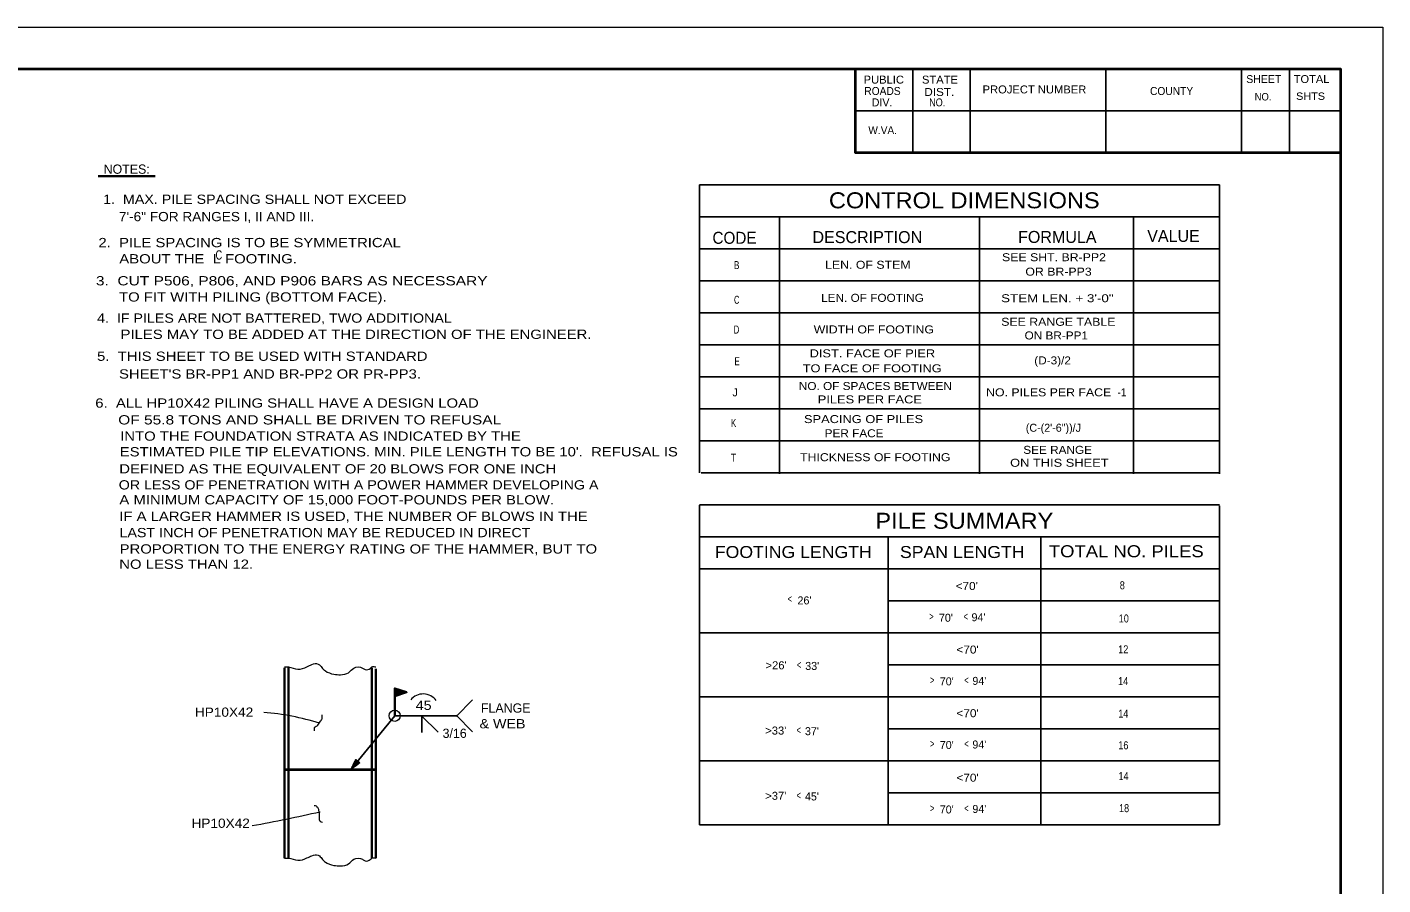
# Model space of a CAD drawing. Extents: x 144 to 252, y 360 to 425.
# Drawn here: x 203.8 to 251.81, y 395.1 to 425.48 of the extents above; entities that cross this region are included whole.
import ezdxf
from ezdxf.enums import TextEntityAlignment as Align

# ---------------------------------------------------------------- set-up
doc = ezdxf.new("R2010")
doc.units = 0
doc.header["$LTSCALE"] = 0.13
for name, color, linetype, lineweight in [('1', 7, 'Continuous', 40), ('16', 7, 'Continuous', 13), ('18', 7, 'Continuous', 13), ('3', 7, 'Continuous', 13), ('30', 7, 'Continuous', 35), ('5', 7, 'Continuous', 35)]:
    doc.layers.add(name, color=color, linetype=linetype, lineweight=lineweight)

msp = doc.modelspace()

# ---------------------------------------------------------------- linework, layer by layer
at = {"layer": '1', "lineweight": 13}
msp.add_line((143.8112, 425.4823), (251.8112, 425.4823), dxfattribs=at)
at = {"layer": '1', "lineweight": 25}
for p, q in [((235.1642, 423.9913), (235.1642, 421.0393)), ((237.2012, 423.9913), (237.2012, 421.0393)), ((242.0042, 423.9913), (242.0042, 421.0393)), ((246.8012, 423.9913), (246.8012, 421.0393)), ((248.5052, 423.9913), (248.5052, 421.0393)), ((233.1242, 422.5183), (250.3172, 422.5183)), ((227.6108, 419.8997), (246.0275, 419.8997)), ((227.6108, 419.8997), (227.6108, 409.6906)), ((246.0275, 419.8997), (246.0275, 409.6627)), ((227.6108, 418.7607), (246.0275, 418.7607)), ((230.4442, 418.7607), (230.4442, 409.6627)), ((237.5275, 418.7607), (237.5275, 409.6627)), ((242.9788, 418.7607), (242.9788, 409.6627)), ((227.6108, 417.6273), (246.0275, 417.6273)), ((227.6108, 416.494), (246.0275, 416.494)), ((227.6108, 415.3607), (246.0275, 415.3607)), ((227.6108, 414.2273), (246.0275, 414.2273)), ((227.6108, 413.094), (246.0275, 413.094)), ((227.6108, 411.9607), (246.0275, 411.9607)), ((227.6108, 410.8273), (246.0275, 410.8273)), ((227.6762, 409.694), (246.0275, 409.694)), ((227.6108, 408.5607), (246.0275, 408.5607)), ((227.6108, 408.547), (227.6108, 397.2273)), ((246.0275, 408.5192), (246.0275, 397.2273)), ((227.6108, 407.4273), (246.0275, 407.4273)), ((234.2933, 407.4313), (234.2933, 397.2273)), ((239.7031, 407.4034), (239.7031, 397.2273)), ((227.6108, 406.294), (246.0275, 406.294)), ((234.2696, 405.1607), (246.0275, 405.1607)), ((234.2935, 405.1607), (246.0275, 405.1607)), ((227.6108, 404.0273), (246.0275, 404.0273)), ((227.6108, 404.0273), (246.0275, 404.0273)), ((234.2696, 402.894), (246.0275, 402.894)), ((234.2935, 402.894), (246.0275, 402.894)), ((227.6108, 401.7607), (246.0275, 401.7607)), ((234.2703, 400.6273), (246.0275, 400.6273)), ((227.6108, 399.494), (246.0275, 399.494)), ((234.2703, 398.3607), (246.0275, 398.3607)), ((227.6108, 397.2273), (246.0275, 397.2273))]:
    msp.add_line(p, q, dxfattribs=at)
at = {"layer": '1'}
for points in [[(250.3172, 361.9183), (250.3172, 423.9913), (149.8112, 423.9913), (149.8112, 361.9183), (230.3642, 361.9183)], [(233.1242, 423.9913), (233.1242, 421.0393), (250.3172, 421.0393)]]:
    msp.add_lwpolyline(points, dxfattribs=at)
at = {"layer": '16'}
msp.add_line((251.8112, 425.4823), (251.8112, 360.4183), dxfattribs=at)
at = {"layer": '18', "lineweight": 40}
msp.add_line((212.8978, 399.1897), (216.1891, 399.1897), dxfattribs=at)
at = {"layer": '18'}
msp.add_circle((216.8197, 401.0882), 0.1992, dxfattribs=at)
for centre, radius, start, end in [((217.8308, 401.2918), 0.5699, 36.25159, 141.15152), ((211.561, 392.7422), 8.487, 72.16357, 85.80287), ((199.8884, 461.4898), 65.3832, 280.4785, 282.62405)]:
    msp.add_arc(centre, radius, start, end, dxfattribs=at)
for points in [[(213.9855, 400.5587), (214.003, 400.6987), (214.0731, 400.7337), (214.1256, 400.7862), (214.2132, 400.9263), (214.2482, 400.9788), (214.2482, 401.0664), (214.2482, 401.1189)], [(213.968, 397.9148), (214.038, 397.8973), (214.0556, 397.8798), (214.1081, 397.8098), (214.1256, 397.7398), (214.1431, 397.6347), (214.1431, 397.5822), (214.1431, 397.4772), (214.1781, 397.3546), (214.2657, 397.3196)]]:
    msp.add_spline(points, degree=3, dxfattribs=at)
at = {"layer": '3', "lineweight": 25}
for p, q in [((219.5754, 401.6492), (218.9924, 401.0667)), ((216.8234, 401.0874), (215.2632, 399.1897)), ((216.8234, 401.0874), (219.0234, 401.0874)), ((218.3567, 400.5062), (217.7739, 401.0887)), ((217.7802, 400.4942), (217.7802, 401.0942)), ((219.5752, 400.5254), (218.9924, 401.1079))]:
    msp.add_line(p, q, dxfattribs=at)
at = {"layer": '3'}
msp.add_line((215.4387, 399.5452), (215.2567, 399.1742), dxfattribs=at)
at = {"layer": '3', "lineweight": 35}
msp.add_lwpolyline([(216.8234, 401.0874), (216.8234, 402.0596), (217.2401, 401.9207), (216.8234, 401.7818), (216.8374, 402.0304), (217.2093, 401.9228), (216.8393, 401.8038), (216.8432, 402.006), (217.1621, 401.9247), (216.8467, 401.8173), (216.8564, 401.9796), (217.1093, 401.9247), (216.8602, 401.8341), (216.8677, 401.9494), (217.0602, 401.9211), (216.877, 401.8511), (216.8827, 401.9324), (216.9998, 401.9192), (216.8734, 401.8643), (216.894, 401.9077), (216.9582, 401.9153), (216.9073, 401.8926)], dxfattribs=at)
at = {"layer": '3'}
msp.add_lwpolyline([(215.4417, 399.5422), (215.5854, 399.4247), (215.2567, 399.1742)], dxfattribs=at)
at = {"layer": '3', "lineweight": 25}
for points in [[(215.5704, 399.4284), (215.2854, 399.2064), (215.5527, 399.4449), (215.2914, 399.2252), (215.5307, 399.4559), (215.3094, 399.2489), (215.5182, 399.4587), (215.3067, 399.2679), (215.5017, 399.4649), (215.3377, 399.3102), (215.4584, 399.4527), (215.3459, 399.3292), (215.4554, 399.4734), (215.3564, 399.3532), (215.4414, 399.4832), (215.3749, 399.3802), (215.4294, 399.4912), (215.3719, 399.4009)], [(215.3862, 399.4204), (215.2894, 399.2159), (215.3602, 399.3357)], [(215.5424, 399.4167), (215.4484, 399.3512), (215.5164, 399.3959), (215.4027, 399.3134), (215.4889, 399.4277), (215.3819, 399.3507), (215.4667, 399.4717), (215.3919, 399.3919), (215.4672, 399.4384), (215.3877, 399.3644), (215.5182, 399.4274)], [(215.4944, 399.4029), (215.4257, 399.3549), (215.5097, 399.4327), (215.3707, 399.3034)], [(215.5092, 399.4837), (215.5682, 399.4259), (215.4462, 399.5294), (215.5502, 399.4222), (215.4307, 399.5222), (215.5544, 399.4094), (215.4282, 399.5079), (215.5414, 399.4002), (215.4232, 399.4972), (215.5329, 399.3922)]]:
    msp.add_spline(points, degree=3, dxfattribs=at)
at = {"layer": '30'}
msp.add_line((206.3227, 420.2052), (208.3405, 420.2052), dxfattribs=at)
at = {"layer": '5'}
for p, q in [((212.9222, 402.7922), (212.9225, 396.047)), ((213.0621, 402.7922), (213.0623, 396.0469)), ((216.0155, 402.7922), (216.0157, 396.0472)), ((216.1554, 402.7482), (216.1557, 396.0471))]:
    msp.add_line(p, q, dxfattribs=at)
at = {"layer": '5', "lineweight": 13}
for points in [[(212.9225, 402.8192), (213.0623, 402.8191), (213.3893, 402.7417), (213.7145, 402.823), (213.8859, 402.9043), (214.1117, 402.9222), (214.1568, 402.8954), (214.2651, 402.7689), (214.3646, 402.6787), (214.6623, 402.5611), (214.8974, 402.5432), (215.1862, 402.6154), (215.3757, 402.7779), (215.6828, 402.7781), (215.7731, 402.7237), (215.9538, 402.7688), (216.0157, 402.8193), (216.1557, 402.8193)], [(212.9225, 396.047), (213.0623, 396.0469), (213.3893, 395.9695), (213.7145, 396.0508), (213.8859, 396.1322), (214.1117, 396.1501), (214.1568, 396.1232), (214.2651, 395.9967), (214.3646, 395.9065), (214.6623, 395.7889), (214.8974, 395.771), (215.1862, 395.8433), (215.3757, 396.0057), (215.6828, 396.0059), (215.7731, 395.9515), (215.9538, 395.9967), (216.0157, 396.0472), (216.1557, 396.0471)]]:
    msp.add_spline(points, degree=3, dxfattribs=at)

# ---------------------------------------------------------------- texts
at = {"layer": '1'}
for s, height, width, p in [('PUBLIC', 0.282, 1.05, (234.1385, 423.4813)), ('STATE', 0.282, 1.05, (236.1275, 423.4813)), ('PROJECT NUMBER', 0.282, 1.05, (239.4737, 423.1333)), ('TOTAL', 0.2791, 1.05, (249.2858, 423.5023)), ('ROADS', 0.285, 0.95, (234.0921, 423.0763)), ('DIST.', 0.282, 1.1, (236.1036, 423.0433)), ('NO.', 0.282, 0.85, (236.0299, 422.6743)), ('COUNTY', 0.285, 0.95, (244.3296, 423.0763)), ('NO.', 0.264, 0.95, (247.5679, 422.8843)), ('SHTS', 0.261, 1.1, (249.2505, 422.9053)), ('W.VA.', 0.282, 0.95, (234.0992, 421.6903)), ('NO. OF SPACES BETWEEN', 0.2833, 1.1, (233.8403, 412.6273)), ('PILES PER FACE', 0.2833, 1.2, (233.6452, 412.1532)), ('NO. PILES PER FACE', 0.2833, 1.15, (239.9767, 412.4042)), ('-1', 0.2833, 0.95, (242.5707, 412.4042)), ('K', 0.2833, 0.75, (228.8199, 411.3164)), ('SPACING OF PILES', 0.2833, 1.2, (233.422, 411.4558)), ('PER FACE', 0.2833, 1.1, (233.0873, 410.9538)), ('SEE RANGE', 0.2833, 1.1, (240.2944, 410.3659)), ('T', 0.2833, 0.8, (228.8199, 410.0848)), ('THICKNESS OF FOOTING', 0.2833, 1.15, (233.8362, 410.1062)), ('ON THIS SHEET', 0.2833, 1.2, (240.3544, 409.9088))]:
    msp.add_text(s, height=height, dxfattribs=dict(at, width=width)).set_placement(p, align=Align.CENTER)
for s, height, p in [('SHEET', 0.2791, (247.5948, 423.5023)), ('DIV.', 0.282, (234.0783, 422.6743)), ('J', 0.2833, (228.8756, 412.4042)), ('(C-(2\'-6"))/J', 0.2833, (240.144, 411.149))]:
    msp.add_text(s, height=height, dxfattribs=at).set_placement(p, align=Align.CENTER)
for s, height, width, p in [('CONTROL DIMENSIONS', 0.5667, 1.1, (232.1952, 419.0638)), ('CODE', 0.425, 0.95, (228.0727, 417.8058)), ('B', 0.2833, 0.75, (228.835, 416.9092)), ('LEN. OF STEM', 0.2833, 1.15, (232.0607, 416.9223)), ('SEE SHT. BR-PP2', 0.2833, 1.15, (238.3252, 417.1897)), ('OR BR-PP3', 0.2833, 1.15, (239.1519, 416.6783)), ('C', 0.2833, 0.65, (228.835, 415.6819)), ('LEN. OF FOOTING', 0.2833, 1.1, (231.9213, 415.7509)), ('STEM LEN. + 3\'-0"', 0.2833, 1.25, (238.2929, 415.7367)), ('D', 0.2833, 0.65, (228.8284, 414.628)), ('WIDTH OF FOOTING', 0.2833, 1.15, (231.657, 414.6318)), ('SEE RANGE TABLE', 0.2833, 1.15, (238.2973, 414.9025)), ('ON BR-PP1', 0.2833, 1.1, (239.124, 414.4191)), ('DIST. FACE OF PIER', 0.2833, 1.2, (231.5117, 413.7842)), ('(D-3)/2', 0.2833, 1.1, (239.4676, 413.5342)), ('E', 0.2833, 0.75, (228.8502, 413.5051)), ('TO FACE OF FOOTING', 0.2833, 1.2, (231.266, 413.2544)), ('PILE SUMMARY', 0.5667, 1.1, (233.8408, 407.7117)), ('FOOTING LENGTH', 0.425, 1.1, (228.1563, 406.6768)), ('SPAN LENGTH', 0.425, 1.1, (234.711, 406.6767)), ('TOTAL NO. PILES', 0.425, 1.15, (239.9827, 406.7047)), ("<70'", 0.2833, 1.1, (236.6829, 405.5454)), ('8', 0.2833, 0.85, (242.4947, 405.5699)), ('<', 0.2833, 0.65, (230.737, 405.0905)), ('>', 0.2833, 0.65, (235.7448, 404.4672)), ('<', 0.2833, 0.65, (236.9617, 404.4646)), ('10', 0.2833, 0.85, (242.4577, 404.3938)), ("<70'", 0.2833, 1.1, (236.7129, 403.2917)), ('12', 0.2833, 0.85, (242.4385, 403.3004)), (">26'", 0.2833, 1.05, (229.9488, 402.7347)), ('<', 0.2833, 0.65, (231.0592, 402.7532)), ('>', 0.2833, 0.65, (235.7748, 402.2136)), ('<', 0.2833, 0.65, (236.9917, 402.2109)), ('14', 0.2833, 0.85, (242.4357, 402.1735)), ("<70'", 0.2833, 1.1, (236.7129, 401.0381)), ('14', 0.2833, 0.85, (242.4398, 401.0231)), (">33'", 0.2833, 1.05, (229.939, 400.4234)), ('<', 0.2833, 0.65, (231.0493, 400.4418)), ('>', 0.2833, 0.65, (235.7748, 399.9599)), ('<', 0.2833, 0.65, (236.9917, 399.9572)), ('16', 0.2833, 0.85, (242.4424, 399.9002)), ("<70'", 0.2833, 1.1, (236.7129, 398.7543)), ('14', 0.2833, 0.85, (242.4492, 398.8111)), (">37'", 0.2833, 1.05, (229.939, 398.1121)), ('<', 0.2833, 0.65, (231.0493, 398.1305)), ('>', 0.2833, 0.65, (235.7748, 397.6762)), ('<', 0.2833, 0.65, (236.9917, 397.6735)), ('18', 0.2833, 0.85, (242.4682, 397.6744))]:
    msp.add_text(s, height=height, dxfattribs=dict(at, width=width)).set_placement(p)
for s, height, p in [('DESCRIPTION ', 0.425, (231.6143, 417.8313)), ('FORMULA', 0.425, (238.8932, 417.837)), ('VALUE', 0.425, (243.4662, 417.8738)), ("26'", 0.2833, (231.0834, 405.0333)), ("70'", 0.2833, (236.0912, 404.4195)), ("94'", 0.2833, (237.2452, 404.4367)), ("33'", 0.2833, (231.3573, 402.7126)), ("70'", 0.2833, (236.1212, 402.1658)), ("94'", 0.2833, (237.2752, 402.1831)), ("37'", 0.2833, (231.3475, 400.4013)), ("70'", 0.2833, (236.1212, 399.9122)), ("94'", 0.2833, (237.2752, 399.9294)), ("45'", 0.2833, (231.3475, 398.0899)), ("70'", 0.2833, (236.1212, 397.6284)), ("94'", 0.2833, (237.2752, 397.6457))]:
    msp.add_text(s, height=height, dxfattribs=at).set_placement(p)
at = {"layer": '18', "width": 1.1}
for p in [(211.8116, 401.0532), (211.6908, 397.1188)]:
    msp.add_text('HP10X42', height=0.3281, dxfattribs=at).set_placement(p, align=Align.RIGHT)
at = {"layer": '18', "width": 1.15}
msp.add_text('45', height=0.3281, dxfattribs=at).set_placement((217.8458, 401.2945), align=Align.CENTER)
at = {"layer": '18'}
msp.add_text('FLANGE', height=0.3281, dxfattribs=at).set_placement((219.8733, 401.198))
at = {"layer": '18', "width": 1.15}
msp.add_text('& WEB', height=0.3281, dxfattribs=at).set_placement((219.8251, 400.6428))
at = {"layer": '18'}
msp.add_text('3/16', height=0.3281, dxfattribs=at).set_placement((218.9429, 400.3049), align=Align.CENTER)
at = {"layer": '30'}
msp.add_text('NOTES:', height=0.3281, dxfattribs=at).set_placement((206.5136, 420.2871))
for s, width, p in [('1.  MAX. PILE SPACING SHALL NOT EXCEED', 1.15, (206.4971, 419.2203)), ('7\'-6" FOR RANGES I, II AND III.', 1.1, (207.0549, 418.6067)), ('2.  PILE SPACING IS TO BE SYMMETRICAL', 1.2, (206.3297, 417.6862)), ('ABOUT THE  L FOOTING.', 1.2, (207.0692, 417.1116)), ('C', 0.75, (210.4751, 417.2479)), ('3.  CUT P506, P806, AND P906 BARS AS NECESSARY', 1.25, (206.2409, 416.3329)), ('TO FIT WITH PILING (BOTTOM FACE).', 1.2, (207.0589, 415.7603)), ('4.  IF PILES ARE NOT BATTERED, TWO ADDITIONAL ', 1.15, (206.2818, 415.0104)), ('PILES MAY TO BE ADDED AT THE DIRECTION OF THE ENGINEER.', 1.2, (207.1134, 414.4378)), ('5.  THIS SHEET TO BE USED WITH STANDARD', 1.2, (206.2817, 413.6608)), ("SHEET'S BR-PP1 AND BR-PP2 OR PR-PP3.", 1.2, (207.0589, 413.0331)), ('6.  ALL HP10X42 PILING SHALL HAVE A DESIGN LOAD', 1.2, (206.2182, 412.0018)), ('OF 55.8 TONS AND SHALL BE DRIVEN TO REFUSAL', 1.25, (207.0303, 411.4072)), ('INTO THE FOUNDATION STRATA AS INDICATED BY THE', 1.2, (207.0997, 410.8311)), ("ESTIMATED PILE TIP ELEVATIONS. MIN. PILE LENGTH TO BE 10'.  REFUSAL IS ", 1.2, (207.0857, 410.2757)), ('DEFINED AS THE EQUIVALENT OF 20 BLOWS FOR ONE INCH', 1.2, (207.0673, 409.6719)), ('OR LESS OF PENETRATION WITH A POWER HAMMER DEVELOPING A ', 1.15, (207.0482, 409.1037)), ('A MINIMUM CAPACITY OF 15,000 FOOT-POUNDS PER BLOW.', 1.2, (207.0718, 408.575)), ('IF A LARGER HAMMER IS USED, THE NUMBER OF BLOWS IN THE', 1.2, (207.0673, 407.9919)), ('LAST INCH OF PENETRATION MAY BE REDUCED IN DIRECT ', 1.15, (207.0766, 407.4135)), ('PROPORTION TO THE ENERGY RATING OF THE HAMMER, BUT TO', 1.2, (207.0811, 406.835)), ('NO LESS THAN 12.', 1.2, (207.0673, 406.2936))]:
    msp.add_text(s, height=0.3281, dxfattribs=dict(at, width=width)).set_placement(p)

doc.saveas('drawing.dxf')
